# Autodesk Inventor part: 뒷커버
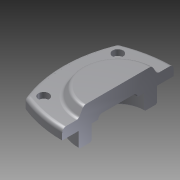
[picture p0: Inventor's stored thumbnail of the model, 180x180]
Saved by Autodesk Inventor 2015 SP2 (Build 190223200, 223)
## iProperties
Created: 2013-02
Part Number: 뒷커버
Document SubType Name: Modeling
Designer: 한국산업디자인학원[gmhk.co.kr]
Density: 1 g/cm^3
Material: 일반
Appearance: 기본값
Author: 한국산업디자인학원[gmhk.co.kr]
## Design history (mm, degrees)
sketch "스케치1"
  geometry: C1 r 30 at (0, 0) reference; A1 r 91.05 centre (0, -48.55) between (34.185, 35.839) and (-34.185, 35.839) reference; A2 r 91.05 centre (48.55, 0) between (-35.839, 34.185) and (-35.839, -34.185) reference; A3 r 3 centre (-33.058, 33.058) between (-34.185, 35.839) and (-35.839, 34.185) reference; A4 r 3 centre (33.058, 33.058) between (35.839, 34.185) and (34.185, 35.839) reference; A5 r 91.05 centre (-48.55, 0) between (35.839, -34.185) and (35.839, 34.185) reference; A6 r 3 centre (33.058, -33.058) between (34.185, -35.839) and (35.839, -34.185) reference; A7 r 91.05 centre (0, 48.55) between (-34.185, -35.839) and (34.185, -35.839) reference; A8 r 3 centre (-33.058, -33.058) between (-35.839, -34.185) and (-34.185, -35.839) reference; 1 further point
  node "참조1"
  node "참조2"
  node "참조3"
  node "참조4"
  node "참조5"
  node "참조6"
  node "참조7"
  node "참조8"
  node "참조9"
extrude "돌출1" new body sketch "스케치1" distance "d0" = 8; taper "d1" = 0 deg
sketch "스케치2"
  geometry: C1 r 30 at (0, 0); 1 further point
  constraints: 1 centre point, 1 coincident
  dimensions: "d2" = 60 diameter of C1
extrude "돌출2" join sketch "스케치2" distance "d3" = 7; taper "d4" = -30 deg
sketch "스케치3"
  geometry: C1 r 1.621 at (28.284, 28.284) reference; C2 r 1.621 at (-28.284, 28.284) reference; C3 r 1.621 at (-28.284, -28.284) reference; C4 r 1.621 at (28.284, -28.284) reference; 1 further point
hole "구멍2" sketch "스케치3" at (28.284, 28.284), (28.284, -28.284), (-28.284, -28.284), (-28.284, 28.284) diameter "d14" = 4.5; stored, may be unused: countersink angle "d18" = 90 deg, drill point angle "d20" = 118 deg; dims "d15" = 6, "d16" = 8, "d17" = 4.4, "d19" = 20
extrude "돌출3" join sketch "스케치1" distance "d21" = 12; taper "d22" = 0 deg
hole "구멍3" diameter "d25" = 30; stored, may be unused: countersink angle "d29" = 90 deg, drill point angle "d31" = 0 deg; dims "d23" = 10, "d24" = 10, "d26" = 6, "d27" = 40, "d28" = 12, "d30" = 15
fillet "모깎기1" dims "d32" = 3, "d33" = 0.3
chamfer "모따기1" distance "d34" = 1; stored, may be unused: second distance "d35" = 2, angle "d36" = 45 deg
sketch "스케치4"
  geometry: L1 (0, 47.073)-(63.397, 47.073); L2 (63.397, 47.073)-(63.397, -47.548); L3 (63.397, -47.548)-(0, -47.548); L4 (0, -47.548)-(0, 47.073); 1 further point
  constraints: 8 end point, 2 parallel, 1 horizontal, 1 perpendicular
extrude "돌출4" cut sketch "스케치4" distance "d37" = 123; taper "d38" = 0 deg
node "솔리드1"
node "참조10"
node "참조11"
node "참조12"
node "참조13"
